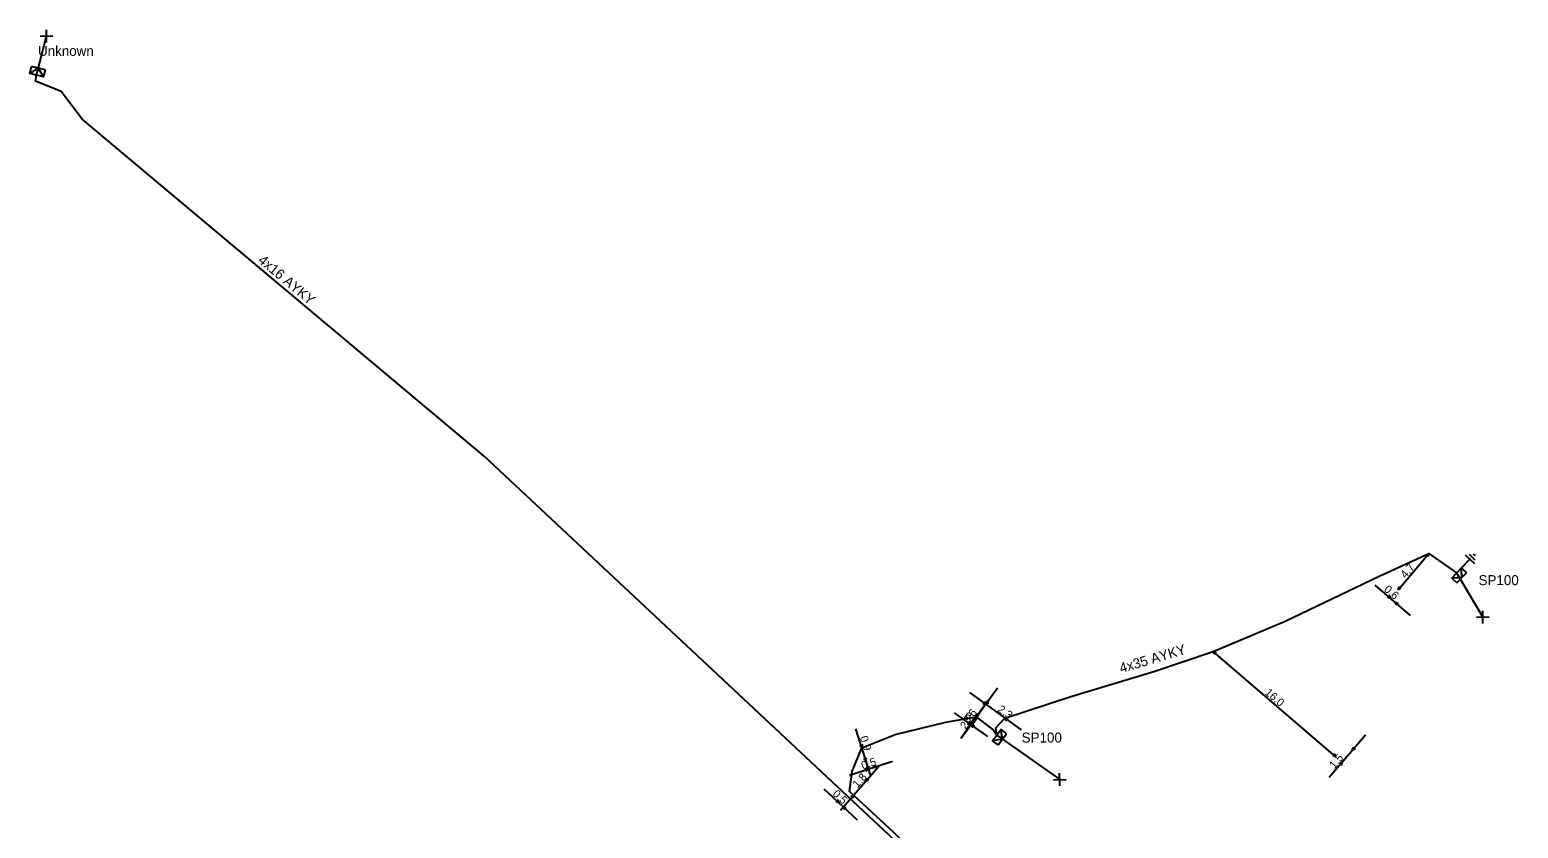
# Model space of a CAD drawing. Extents: x -762284 to -761419, y -1155250 to -1154991.
# Drawn here: x -761883.1 to -761735.1, y -1155100.2 to -1155020.9 of the extents above; entities that cross this region are included whole.
import ezdxf

# ---------------------------------------------------------------- set-up
doc = ezdxf.new("R2010")
doc.units = 0
for name, color, linetype in [('Vrstva 15', 7, 'Continuous'), ('Vrstva 31', 7, 'Continuous'), ('Vrstva 33', 7, 'Continuous'), ('Vrstva 34', 7, 'Continuous'), ('Vrstva 40', 7, 'Continuous'), ('Vrstva 5', 7, 'Continuous'), ('Vrstva 59', 7, 'Continuous'), ('Vrstva 6', 7, 'Continuous')]:
    doc.layers.add(name, color=color, linetype=linetype)

msp = doc.modelspace()

# ---------------------------------------------------------------- linework, layer by layer
at = {"layer": 'Vrstva 15'}
for points in [[(-761740.41, -1155073.033), (-761739.511, -1155073.902)], [(-761740.021, -1155072.978), (-761739.454, -1155073.525)], [(-761739.622, -1155072.926), (-761739.526, -1155073.018)], [(-761739.526, -1155073.018), (-761739.434, -1155073.107)], [(-761740.828, -1155074.367), (-761739.96, -1155073.467)]]:
    msp.add_lwpolyline(points, dxfattribs=at)
at = {"layer": 'Vrstva 31'}
for points in [[(-761881.529, -1155024.861), (-761881.698, -1155025.54), (-761883.057, -1155025.201), (-761882.887, -1155024.522)], [(-761882.208, -1155024.691), (-761883.057, -1155025.201)], [(-761881.529, -1155024.861), (-761882.887, -1155024.522)], [(-761882.208, -1155024.691), (-761881.698, -1155025.54)], [(-761741.254, -1155075.822), (-761741.758, -1155075.336), (-761740.785, -1155074.329), (-761740.282, -1155074.815)], [(-761740.768, -1155075.318), (-761740.785, -1155074.329)], [(-761740.768, -1155075.318), (-761741.758, -1155075.336)], [(-761741.254, -1155075.822), (-761740.282, -1155074.815)], [(-761786.834, -1155091.913), (-761787.393, -1155091.491), (-761786.551, -1155090.373), (-761785.991, -1155090.795)], [(-761786.834, -1155091.913), (-761785.991, -1155090.795)], [(-761786.413, -1155091.354), (-761786.551, -1155090.373)], [(-761786.413, -1155091.354), (-761787.393, -1155091.491)]]:
    msp.add_lwpolyline(points, dxfattribs=at)
at = {"layer": 'Vrstva 34'}
for points in [[(-761881.389, -1155022.115), (-761881.411, -1155020.865)], [(-761882.025, -1155021.501), (-761880.775, -1155021.479)], [(-761738.659, -1155079.835), (-761738.681, -1155078.585)], [(-761739.295, -1155079.221), (-761738.045, -1155079.199)], [(-761780.699, -1155095.985), (-761780.721, -1155094.735)], [(-761781.335, -1155095.371), (-761780.085, -1155095.349)]]:
    msp.add_lwpolyline(points, dxfattribs=at)
at = {"layer": 'Vrstva 40'}
for points in [[(-761747.09, -1155076.49), (-761744.02, -1155072.9)], [(-761745.86, -1155079.04), (-761749.35, -1155076.05)], [(-761753.27, -1155093.08), (-761765.46, -1155082.64)], [(-761786.89, -1155086.27), (-761790.49, -1155091.26)], [(-761790.54, -1155091.23), (-761787.85, -1155087.5)], [(-761789.68, -1155086.72), (-761784.55, -1155090.42)], [(-761791.2, -1155088.73), (-761787.9, -1155091.09)], [(-761799.48, -1155094.99), (-761800.98, -1155090.31)], [(-761750.34, -1155090.93), (-761753.94, -1155095.14)], [(-761801.61, -1155094.91), (-761797.34, -1155093.54)], [(-761802.51, -1155098.4), (-761798.68, -1155094.02)], [(-761800.79, -1155099.39), (-761804.11, -1155096.3)]]:
    msp.add_lwpolyline(points, dxfattribs=at)
for points in [[(-761744.018, -1155072.898), (-761744.098, -1155073.156), (-761744.258, -1155073.021)], [(-761747.828, -1155077.352), (-761748.086, -1155077.272), (-761747.951, -1155077.112)], [(-761747.092, -1155076.492), (-761747.012, -1155076.234), (-761746.852, -1155076.369)], [(-761747.382, -1155077.738), (-761747.124, -1155077.818), (-761747.258, -1155077.978)], [(-761765.462, -1155082.638), (-761765.204, -1155082.718), (-761765.339, -1155082.878)], [(-761788.058, -1155087.892), (-761788.322, -1155087.835), (-761788.202, -1155087.663)], [(-761788.062, -1155087.892), (-761788.005, -1155087.628), (-761787.833, -1155087.748)], [(-761789.022, -1155089.122), (-761788.965, -1155088.858), (-761788.793, -1155088.978)], [(-761786.172, -1155089.248), (-761785.908, -1155089.305), (-761786.028, -1155089.477)], [(-761789.568, -1155089.892), (-761789.832, -1155089.835), (-761789.712, -1155089.664)], [(-761789.368, -1155089.608), (-761789.425, -1155089.872), (-761789.597, -1155089.752)], [(-761789.318, -1155089.638), (-761789.375, -1155089.902), (-761789.547, -1155089.782)], [(-761789.532, -1155089.929), (-761789.269, -1155089.986), (-761789.388, -1155090.157)], [(-761800.369, -1155092.213), (-761800.546, -1155092.008), (-761800.347, -1155091.944)], [(-761751.642, -1155092.452), (-761751.562, -1155092.194), (-761751.402, -1155092.328)], [(-761800.091, -1155093.087), (-761799.914, -1155093.292), (-761800.113, -1155093.356)], [(-761753.268, -1155093.082), (-761753.526, -1155093.002), (-761753.391, -1155092.842)], [(-761752.639, -1155093.618), (-761752.718, -1155093.875), (-761752.879, -1155093.741)], [(-761799.697, -1155094.3), (-761799.901, -1155094.476), (-761799.966, -1155094.277)], [(-761799.242, -1155094.151), (-761799.038, -1155093.975), (-761798.973, -1155094.173)], [(-761800.002, -1155095.532), (-761799.918, -1155095.276), (-761799.76, -1155095.413)], [(-761802.648, -1155097.671), (-761802.903, -1155097.583), (-761802.763, -1155097.427)], [(-761802.252, -1155098.028), (-761801.997, -1155098.116), (-761802.137, -1155098.272)], [(-761801.198, -1155096.898), (-761801.282, -1155097.154), (-761801.44, -1155097.017)]]:
    msp.add_lwpolyline(points, close=True, dxfattribs=at)
at = {"layer": 'Vrstva 5'}
for points in [[(-761789.53, -1155107.69), (-761789.92, -1155108.14), (-761837.9, -1155063.24), (-761877.84, -1155029.75), (-761879.95, -1155027.01), (-761882.5, -1155025.98), (-761882.38, -1155025.37)], [(-761789.65, -1155107.58), (-761789.97, -1155107.81), (-761794.53, -1155103.25), (-761797.17, -1155100.64), (-761801.59, -1155096.53), (-761801.33, -1155094.57), (-761800.37, -1155092.21), (-761797.07, -1155090.87), (-761792.02, -1155089.66), (-761789.02, -1155089.12), (-761787.3, -1155090.45), (-761786.97, -1155090.93), (-761787.05, -1155090.2), (-761786.17, -1155089.25), (-761779.7, -1155087.13), (-761771.35, -1155084.63), (-761765.46, -1155082.64), (-761758.32, -1155079.63), (-761748.98, -1155075.15), (-761744.02, -1155072.9), (-761741.27, -1155074.83)]]:
    msp.add_lwpolyline(points, dxfattribs=at)
at = {"layer": 'Vrstva 59'}
for points in [[(-761882.38, -1155025.37), (-761881.4, -1155021.49)], [(-761741.27, -1155074.83), (-761738.67, -1155079.21)], [(-761786.97, -1155090.93), (-761780.71, -1155095.36)]]:
    msp.add_lwpolyline(points, dxfattribs=at)

# ---------------------------------------------------------------- texts
at = {"layer": 'Vrstva 33'}
for s, p in [('Unknown', (-761882.24, -1155023.46)), ('SP100', (-761739.09, -1155076.04)), ('SP100', (-761784.49, -1155091.68))]:
    msp.add_text(s, height=0.9943, dxfattribs=at).set_placement(p)
at = {"layer": 'Vrstva 40'}
for s, rotation, p in [('4,7', 49.42578, (-761746.34, -1155075.42)), ('0,6', 319.44924, (-761748.56, -1155076.57)), ('16,0', 319.43763, (-761760.39, -1155086.82)), ('2,2', 54.21864, (-761790.04, -1155090.43)), ('0,6', 54.26634, (-761789.74, -1155089.91)), ('0,1', 324.45387, (-761790.32, -1155089.21)), ('2,3', 324.21227, (-761786.96, -1155088.53)), ('0,9', 287.76714, (-761800.58, -1155091.16)), ('0,5', 17.75679, (-761800.29, -1155094.36)), ('1,5', 49.43585, (-761753.42, -1155094.34)), ('1,8', 48.7966, (-761800.79, -1155096.25)), ('0,5', 317.10831, (-761803.34, -1155096.86))]:
    msp.add_text(s, height=0.7954, rotation=rotation, dxfattribs=at).set_placement(p)
at = {"layer": 'Vrstva 6'}
for s, rotation, p in [('4x16 AYKY', 320.02779, (-761860.45, -1155043.9)), ('4x35 AYKY', 16.66776, (-761774.61, -1155084.79))]:
    msp.add_text(s, height=0.9943, rotation=rotation, dxfattribs=at).set_placement(p)

doc.saveas('drawing.dxf')
